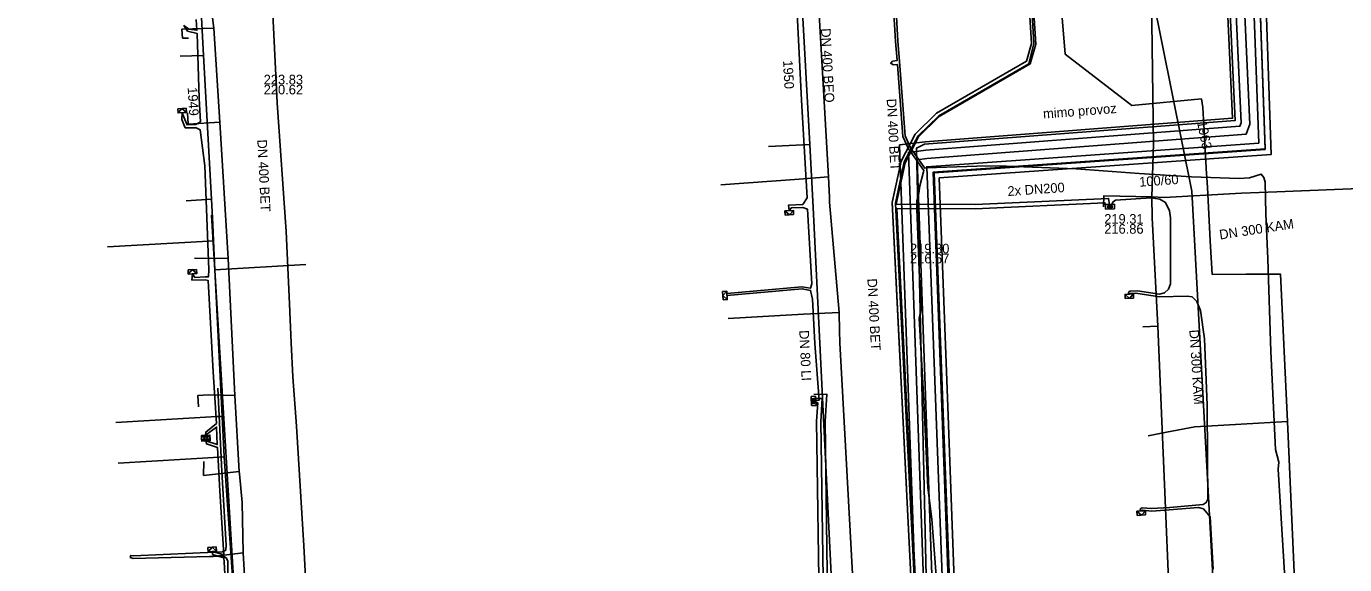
# Model space of a CAD drawing. Extents: x -599951 to -598963, y -1164095 to -1162939.
# Drawn here: x -599392 to -599282.6, y -1163043.2 to -1162998.5 of the extents above; entities that cross this region are included whole.
import ezdxf

# ---------------------------------------------------------------- set-up
doc = ezdxf.new("R2010")
doc.units = 0
for name, color, linetype in [('28', 7, 'Continuous'), ('31', 7, 'Continuous'), ('Vrstva 12', 7, 'Continuous'), ('Vrstva 13', 7, 'Continuous'), ('Vrstva 15', 7, 'Continuous'), ('Vrstva 19', 7, 'Continuous'), ('Vrstva 25', 7, 'Continuous'), ('Vrstva 26', 7, 'Continuous'), ('Vrstva 28', 7, 'Continuous'), ('Vrstva 37', 7, 'Continuous'), ('Vrstva 38', 7, 'Continuous'), ('Vrstva 41', 7, 'Continuous'), ('Vrstva 42', 7, 'Continuous'), ('Vrstva 43', 7, 'Continuous'), ('Vrstva 44', 7, 'Continuous'), ('Vrstva 55', 7, 'Continuous')]:
    doc.layers.add(name, color=color, linetype=linetype)

# ---------------------------------------------------------------- blocks, each defined once
blk = doc.blocks.new('NN630')
at = {"layer": '31'}
for points in [[(-0.003, -0.7), (-0.703, 0)], [(-0.703, -0.7), (-0.703, 0), (0.697, 0), (0.697, -0.7)], [(-0.003, -0.7), (0.697, 0)], [(-0.703, -0.7), (0.697, -0.7)]]:
    blk.add_lwpolyline(points, dxfattribs=at)
blk = doc.blocks.new('NN620')
at = {"layer": '28'}
for points in [[(0.752, 0.004), (-0.748, 0.004)], [(-0.748, 0.004), (-0.748, -0.746)], [(0.752, -0.746), (0.752, 0.004)], [(-0.748, -0.746), (0.752, -0.746)], [(0.368, -0.18), (-0.376, -0.18)], [(-0.376, -0.18), (-0.376, -0.558)], [(-0.376, -0.558), (0.368, -0.558)], [(0.321, -0.227), (-0.329, -0.227)], [(-0.329, -0.227), (-0.329, -0.51)], [(-0.329, -0.51), (0.321, -0.51)], [(0.274, -0.274), (-0.281, -0.274)], [(-0.281, -0.274), (-0.281, -0.463)], [(-0.281, -0.463), (0.274, -0.463)], [(0.227, -0.321), (-0.234, -0.321)], [(-0.234, -0.321), (-0.234, -0.416)], [(-0.234, -0.416), (0.227, -0.416)], [(-0.193, -0.369), (0.185, -0.369)], [(0.227, -0.416), (0.227, -0.321)], [(0.274, -0.463), (0.274, -0.274)], [(0.321, -0.51), (0.321, -0.227)], [(0.368, -0.558), (0.368, -0.18)]]:
    blk.add_lwpolyline(points, dxfattribs=at)

msp = doc.modelspace()

# ---------------------------------------------------------------- linework, layer by layer
at = {"layer": 'Vrstva 12'}
msp.add_lwpolyline([(-599376.65, -1163014.17), (-599374.24, -1163053.96), (-599375.34, -1163054.02), (-599372.81, -1163104.13), (-599372.73, -1163105.83), (-599379.12, -1163106.22), (-599392.02, -1163106.91), (-599391.55, -1163104.38)], dxfattribs=at)
at = {"layer": 'Vrstva 13'}
for p, q in [((-599377.319, -1163000.888), (-599379.255, -1163000.969)), ((-599326.948, -1163008.293), (-599330.381, -1163008.477)), ((-599376.655, -1163012.839), (-599378.763, -1163012.969)), ((-599376.367, -1163018.71), (-599368.809, -1163018.281))]:
    msp.add_line(p, q, dxfattribs=at)
for points in [[(-599376.539, -1163014.958), (-599376.655, -1163012.839), (-599377.319, -1163000.888), (-599378.171, -1162984.588), (-599378.45, -1162980.06), (-599378.82, -1162974.23), (-599379.15, -1162967.72), (-599379.452, -1162962.026), (-599380.077, -1162950.799), (-599380.39, -1162945.01), (-599380.421, -1162944.491), (-599380.722, -1162939.4)], [(-599326.68, -1163013.53), (-599326.948, -1163008.293), (-599327.64, -1162995.76), (-599328.043, -1162987.835), (-599328.151, -1162986.54), (-599328.478, -1162980.575), (-599328.799, -1162974.276), (-599329.08, -1162968.678), (-599329.394, -1162962.653), (-599329.655, -1162956.664), (-599329.88, -1162951.055)], [(-599287.66, -1163147.47), (-599287.596, -1163147.153), (-599291.469, -1163082.154), (-599292.48, -1163063.001), (-599295.243, -1163012.163), (-599300.148, -1162987.801), (-599300.278, -1162987.115), (-599302.071, -1162951.135)], [(-599319.824, -1163142.407), (-599319.759, -1163142.094), (-599323.979, -1163068.87), (-599326.68, -1163013.53)], [(-599370.026, -1163132.931), (-599369.957, -1163132.609), (-599371.633, -1163102.923), (-599371.78, -1163099.83), (-599374.86, -1163044.99), (-599375.586, -1163034.266), (-599375.774, -1163030.889), (-599376.367, -1163018.71), (-599376.476, -1163016.302), (-599376.539, -1163014.958)], [(-599376.476, -1163016.302), (-599376.9, -1163016.326), (-599385.282, -1163016.815)], [(-599375.774, -1163030.889), (-599376.198, -1163030.913), (-599384.58, -1163031.402)], [(-599375.586, -1163034.266), (-599376.01, -1163034.29), (-599384.392, -1163034.779)]]:
    msp.add_lwpolyline(points, dxfattribs=at)
at = {"layer": 'Vrstva 19'}
for points in [[(-599379.168, -1162939.4), (-599379.16, -1162943.1), (-599379.12, -1162943.7), (-599378.94, -1162949.75), (-599378.72, -1162955.7), (-599378.58, -1162957.14), (-599378.39, -1162963.15), (-599378, -1162969.19), (-599377.66, -1162975.24), (-599376.95, -1162984.34), (-599377.05, -1162984.82), (-599377.38, -1162991.49), (-599376.45, -1162998.64), (-599375.963, -1163006.441), (-599375.51, -1163013.7), (-599375.25, -1163017.78), (-599374.71, -1163029.16), (-599374.34, -1163035.46), (-599374.33, -1163035.67), (-599374.09, -1163038.05), (-599374.03, -1163042.23), (-599373.154, -1163056.939)], [(-599329.03, -1162941.398), (-599328.43, -1162946.79), (-599328.44, -1162948.43), (-599328.43, -1162949.96), (-599328.42, -1162952.35), (-599328.46, -1162953.86), (-599328.47, -1162954.08), (-599328.21, -1162957.68), (-599327.88, -1162963.39), (-599327.66, -1162969.43), (-599327.34, -1162975.25), (-599327.15, -1162978.91), (-599327.08, -1162980.4), (-599326.96, -1162981.47), (-599326.52, -1162989.98), (-599326.59, -1162990.17), (-599326.51, -1162991.69), (-599325.41, -1163010.98), (-599325.37, -1163011.57), (-599325.34, -1163012.71), (-599325.32, -1163013.09), (-599324.53, -1163022.27), (-599324.49, -1163023.77)], [(-599305.18, -1162946.96), (-599305.12, -1162950.24), (-599305.28, -1162950.58), (-599308.44, -1162952.65), (-599308.65, -1162953), (-599308.33, -1162968.25), (-599307.74, -1162977.05), (-599307.31, -1162982.96), (-599306.76, -1162988.68), (-599305.75, -1163000.8), (-599300.22, -1163005.05), (-599294.44, -1163004.51), (-599294.34, -1163005.23)], [(-599376.45, -1162998.64), (-599379.113, -1162998.701)], [(-599379.113, -1162998.701), (-599379.05, -1162999.45), (-599378.56, -1162999.45)], [(-599294.34, -1163005.23), (-599294.27, -1163006.21), (-599294.248, -1163006.608), (-599294.02, -1163010.75), (-599293.99, -1163010.99), (-599293.956, -1163011.482), (-599293.93, -1163011.85)], [(-599375.963, -1163006.441), (-599378.584, -1163006.603), (-599378.64, -1163005.68)], [(-599334.34, -1163011.66), (-599327.85, -1163011.19), (-599325.41, -1163010.98)], [(-599293.93, -1163011.85), (-599293.71, -1163016.31), (-599293.55, -1163019.1), (-599290.72, -1163019.08), (-599287.88, -1163019.06), (-599287.29, -1163031.32), (-599286.4, -1163051.37), (-599284.83, -1163084.5), (-599284.03, -1163097.16), (-599283.11, -1163097.11), (-599283.03, -1163098.11)], [(-599375.25, -1163017.78), (-599378.05, -1163017.74)], [(-599333.75, -1163022.75), (-599327.5, -1163022.4), (-599324.53, -1163022.27)], [(-599324.49, -1163023.77), (-599324.46, -1163024.77), (-599323.15, -1163049.03), (-599323.15, -1163049.58), (-599323.13, -1163049.8), (-599323.11, -1163050.08), (-599322.92, -1163053.42), (-599322.91, -1163053.6), (-599322.91, -1163053.64), (-599322.87, -1163053.99), (-599322.88, -1163054.21), (-599322.64, -1163058.55), (-599322.54, -1163060.9), (-599322.42, -1163062.51)], [(-599376.9, -1163029.1), (-599377.786, -1163029.161), (-599377.72, -1163030.11)], [(-599374.71, -1163029.16), (-599376.9, -1163029.1)], [(-599287.29, -1163031.32), (-599295, -1163031.77), (-599297.34, -1163032.2), (-599298.88, -1163032.512)], [(-599377.302, -1163035.804), (-599377.28, -1163034.63)], [(-599374.34, -1163035.46), (-599377.302, -1163035.804)], [(-599374.03, -1163042.23), (-599376.51, -1163042.53), (-599377.639, -1163042.573)]]:
    msp.add_lwpolyline(points, dxfattribs=at)
at = {"layer": 'Vrstva 25'}
msp.add_line((-599299.303, -1163023.441), (-599298.054, -1163023.39), dxfattribs=at)
for points in [[(-599300.733, -1162964.746), (-599300.469, -1162969.62), (-599299.949, -1162980.551), (-599299.608, -1162987.828), (-599299.004, -1162993.074), (-599298.585, -1162996.107), (-599298.467, -1163004.22), (-599298.411, -1163008.238), (-599298.555, -1163012.651)], [(-599290.017, -1162984.479), (-599289.606, -1162996.071), (-599289.16, -1163008.65), (-599316.731, -1163010.607), (-599316.004, -1163030.112), (-599315.215, -1163051.283)], [(-599298.555, -1163012.651), (-599297.531, -1163012.698), (-599291.113, -1163012.346), (-599288.176, -1163012.237), (-599277.923, -1163011.817), (-599272.947, -1163011.498), (-599270.093, -1163011.364), (-599268.714, -1163010.395), (-599267.215, -1163010.078), (-599266.581, -1163009.994), (-599263.155, -1163009.11), (-599262.534, -1163008.77), (-599262.094, -1163004.619), (-599261.61, -1163001.091), (-599260.5, -1163000.959), (-599257.859, -1163000.91), (-599227.32, -1162998.551), (-599226.298, -1162998.669), (-599225.212, -1162998.622), (-599224.037, -1162998.524)], [(-599298.555, -1163012.651), (-599302.544, -1163012.554), (-599302.586, -1163013.486)], [(-599298.555, -1163012.651), (-599298.536, -1163014.387), (-599298.054, -1163023.39)], [(-599298.054, -1163023.39), (-599296.529, -1163059.558)]]:
    msp.add_lwpolyline(points, dxfattribs=at)
at = {"layer": 'Vrstva 26'}
for points in [[(-599315.733, -1163050.809), (-599316.504, -1163030.131), (-599317.248, -1163010.143), (-599289.677, -1163008.185), (-599290.106, -1162996.089), (-599290.517, -1162984.497)], [(-599289.517, -1162984.461), (-599289.106, -1162996.054), (-599288.643, -1163009.115), (-599316.213, -1163011.072), (-599315.504, -1163030.093), (-599314.716, -1163051.265)]]:
    msp.add_lwpolyline(points, dxfattribs=at)
at = {"layer": 'Vrstva 37'}
for points in [[(-599290.485, -1162978.048), (-599290.017, -1162984.479), (-599289.156, -1163008.706), (-599316.634, -1163010.66), (-599315.123, -1163051.266), (-599334.6, -1163052.28), (-599334.32, -1163059.62), (-599376.96, -1163062.17), (-599376.46, -1163077.4), (-599383.092, -1163077.483)], [(-599292.436, -1162978.249), (-599291.143, -1163006.497), (-599291.245, -1163006.778), (-599317.317, -1163008.775), (-599318.78, -1163008.949), (-599316.627, -1163069.826), (-599308.259, -1163069.607)], [(-599292.935, -1162978.272), (-599291.652, -1163006.308), (-599317.451, -1163008.283), (-599318.097, -1163008.6), (-599316.707, -1163069.9), (-599308.159, -1163069.65)]]:
    msp.add_lwpolyline(points, dxfattribs=at)
at = {"layer": 'Vrstva 38'}
for points in [[(-599308.24, -1163070.306), (-599317.302, -1163070.544), (-599319.502, -1163008.33), (-599317.385, -1163008.078), (-599291.861, -1163006.123), (-599293.135, -1162978.281)], [(-599291.737, -1162978.217), (-599290.437, -1163006.604), (-599290.741, -1163007.442), (-599317.249, -1163009.471), (-599318.058, -1163009.568), (-599315.952, -1163069.108), (-599308.277, -1163068.907)]]:
    msp.add_lwpolyline(points, dxfattribs=at)
at = {"layer": 'Vrstva 42'}
for points in [[(-599326.633, -1163029.066), (-599325.551, -1163029.042), (-599325.699, -1163031.314), (-599325.457, -1163048.064), (-599325.288, -1163054.96), (-599318.265, -1163054.466), (-599318.078, -1163053.65), (-599318.348, -1163048.216), (-599318.451, -1163046.377), (-599320.112, -1163013.118), (-599319.388, -1163009.694), (-599318.216, -1163007.447), (-599316.433, -1163005.686), (-599308.957, -1163001.374), (-599308.544, -1162999.916), (-599309.499, -1162984.786), (-599310.569, -1162962.287)], [(-599290.485, -1162978.048), (-599290.017, -1162984.479), (-599289.156, -1163008.706), (-599316.634, -1163010.66), (-599315.123, -1163051.266), (-599334.6, -1163052.28), (-599334.32, -1163059.62), (-599376.96, -1163062.17), (-599376.46, -1163077.4), (-599383.092, -1163077.483)], [(-599302.078, -1163013.294), (-599302.148, -1163012.777), (-599313.241, -1163013.297), (-599319.783, -1163013.256), (-599319.055, -1163009.813), (-599317.931, -1163007.657), (-599316.219, -1163005.967), (-599308.659, -1163001.606), (-599308.191, -1162999.954), (-599309.15, -1162984.766), (-599309.291, -1162981.878), (-599301.679, -1162981.183), (-599285.76, -1162980.219), (-599285.692, -1162978.677)], [(-599292.935, -1162978.272), (-599291.652, -1163006.308), (-599317.451, -1163008.283), (-599318.097, -1163008.6), (-599316.707, -1163069.9), (-599308.159, -1163069.65)], [(-599328.207, -1162993.479), (-599327.641, -1163004.615), (-599327.196, -1163012.72), (-599327.555, -1163013.272), (-599328.739, -1163013.347), (-599328.676, -1163013.796), (-599328.492, -1163013.555), (-599327.546, -1163013.523), (-599327.167, -1163013.667), (-599326.782, -1163019.864), (-599326.91, -1163020.241), (-599327.613, -1163020.122), (-599333.851, -1163020.684), (-599333.843, -1163020.836), (-599327.592, -1163020.282), (-599326.895, -1163020.424), (-599326.733, -1163021.153), (-599326.545, -1163024.846), (-599326.193, -1163029.554), (-599326.471, -1163029.598)], [(-599377.924, -1162997.902), (-599377.856, -1162998.804), (-599378.533, -1162998.701), (-599378.935, -1162998.416), (-599378.628, -1162998.877), (-599377.848, -1162999.069), (-599377.658, -1163004.469), (-599377.564, -1163006.408), (-599377.94, -1163006.645), (-599378.671, -1163006.664), (-599378.853, -1163006.215), (-599379.08, -1163005.653), (-599379.105, -1163006.21), (-599378.83, -1163006.901), (-599377.917, -1163006.9), (-599377.589, -1163007.077), (-599377.201, -1163010.064), (-599376.863, -1163018.698), (-599376.9, -1163019.306), (-599377.171, -1163019.287), (-599378.028, -1163019.343), (-599378.226, -1163019.042), (-599378.278, -1163019.562), (-599377.177, -1163019.556), (-599376.935, -1163019.587), (-599376.51, -1163027.178), (-599376.239, -1163031.481), (-599377.122, -1163032.2), (-599377.131, -1163032.463), (-599376.222, -1163031.786), (-599376.172, -1163033.233), (-599377.105, -1163032.923), (-599377.071, -1163033.184), (-599376.158, -1163033.474), (-599375.961, -1163037.107), (-599375.627, -1163042.385), (-599376.573, -1163042.115), (-599376.559, -1163042.362), (-599375.619, -1163042.633), (-599375.606, -1163042.967), (-599375.312, -1163048.07)], [(-599383.651, -1163066.976), (-599383.04, -1163066.909), (-599382.022, -1163066.204), (-599382.174, -1163059.783), (-599381.318, -1163059.25), (-599375.097, -1163058.41), (-599367.103, -1163057.865), (-599361.976, -1163057.256), (-599337.823, -1163055.997), (-599331.491, -1163055.747), (-599327.851, -1163055.894), (-599326.518, -1163055.909), (-599325.108, -1163055.298), (-599317.982, -1163054.797), (-599317.726, -1163053.681), (-599317.998, -1163048.198), (-599318.101, -1163046.358), (-599319.737, -1163013.607), (-599313.234, -1163013.647), (-599302.452, -1163013.142), (-599302.43, -1163013.302)], [(-599293.47, -1163043.58), (-599293.73, -1163039.24), (-599294.28, -1163038.56), (-599294.68, -1163038.46), (-599297.13, -1163038.66), (-599298.563, -1163038.756), (-599299.329, -1163038.698), (-599299.448, -1163038.752), (-599299.519, -1163038.667), (-599299.491, -1163038.578), (-599299.447, -1163038.519), (-599299.361, -1163038.499), (-599298.583, -1163038.557), (-599297.06, -1163038.47), (-599294.29, -1163038.22), (-599294.05, -1163038.06), (-599293.91, -1163037.77), (-599293.94, -1163034.37), (-599293.98, -1163029.96), (-599294.2, -1163024.44), (-599294.53, -1163022.1), (-599294.82, -1163021.35), (-599295.22, -1163020.97), (-599295.64, -1163020.89), (-599297.93, -1163020.96), (-599299.9, -1163020.664), (-599300.32, -1163020.681), (-599300.439, -1163020.735), (-599300.51, -1163020.65), (-599300.482, -1163020.561), (-599300.438, -1163020.502), (-599300.352, -1163020.482), (-599299.75, -1163020.457), (-599297.92, -1163020.73), (-599297.5, -1163020.63), (-599297.18, -1163020.33), (-599297.01, -1163019.88), (-599297.01, -1163014.38), (-599297.1, -1163013.8), (-599297.43, -1163013.13), (-599297.89, -1163012.83), (-599298.62, -1163012.73), (-599301.592, -1163012.936), (-599301.785, -1163013.05), (-599301.865, -1163013.2), (-599301.865, -1163013.275)], [(-599383.689, -1163066.628), (-599383.231, -1163066.578), (-599382.434, -1163066.081), (-599382.551, -1163059.616), (-599381.439, -1163058.913), (-599375.132, -1163058.062), (-599367.136, -1163057.516), (-599362.006, -1163056.907), (-599337.839, -1163055.647), (-599331.491, -1163055.397), (-599327.842, -1163055.544), (-599326.589, -1163055.558), (-599325.634, -1163055.144), (-599325.807, -1163048.071), (-599326.049, -1163031.305), (-599325.925, -1163029.401), (-599326.626, -1163029.416)], [(-599376.11, -1163028.54), (-599375.78, -1163035.47), (-599375.44, -1163041.6), (-599375.46, -1163042), (-599375.74, -1163042.16), (-599383.11, -1163042.491), (-599383.355, -1163042.445), (-599383.39, -1163042.608), (-599383.14, -1163042.693), (-599375.76, -1163042.51), (-599375.58, -1163042.56), (-599375.43, -1163042.65), (-599375.3, -1163042.9), (-599375.25, -1163048.03)], [(-599326.618, -1163029.766), (-599326.299, -1163029.759), (-599326.399, -1163031.296), (-599326.157, -1163048.078), (-599325.996, -1163054.643)]]:
    msp.add_lwpolyline(points, dxfattribs=at)
at = {"layer": 'Vrstva 44'}
for points in [[(-599318.451, -1163046.377), (-599319.866, -1163018.049), (-599320.112, -1163013.118), (-599319.388, -1163009.694), (-599318.216, -1163007.447), (-599316.433, -1163005.686), (-599308.957, -1163001.374), (-599308.544, -1162999.916), (-599309.499, -1162984.786)], [(-599309.232, -1162984.758), (-599308.369, -1162999.891), (-599308.787, -1163001.599), (-599316.247, -1163005.902), (-599317.975, -1163007.579), (-599319.141, -1163009.74), (-599319.852, -1163013.162), (-599318.18, -1163046.456)]]:
    msp.add_lwpolyline(points, dxfattribs=at)
at = {"layer": 'Vrstva 55'}
for points in [[(-599368.26, -1163055.24), (-599368.99, -1163041.65), (-599369.59, -1163031.7), (-599369.88, -1163027.6), (-599370.04, -1163024.77), (-599370.18, -1163021.55), (-599370.44, -1163015.52), (-599371.19, -1163004.83), (-599371.877, -1162990.601)], [(-599316.28, -1163046.67), (-599316.83, -1163039.44), (-599317.15, -1163036.79), (-599317.49, -1163029.57), (-599317.89, -1163022.77), (-599317.73, -1163021.94), (-599317.89, -1163018.75), (-599318.07, -1163013.64), (-599318.09, -1163012.99), (-599317.9, -1163012.35), (-599317.84, -1163011.74), (-599317.51, -1163010.56), (-599317.506, -1163010.45), (-599318.771, -1163008.651), (-599319.228, -1163007.635), (-599319.692, -1163001.636), (-599320.055, -1163001.683), (-599320.24, -1163001.54), (-599320.089, -1163001.381), (-599319.717, -1163001.33), (-599319.86, -1162999.737), (-599320.17, -1162994.104)], [(-599287.53, -1163044.33), (-599288.07, -1163035.27), (-599288.02, -1163034.69), (-599288.3, -1163033.63), (-599288.67, -1163025.5), (-599288.92, -1163017.79), (-599289.09, -1163014.06), (-599289.15, -1163011.42), (-599289.27, -1163011.04), (-599289.48, -1163010.75), (-599290.46, -1163011.08), (-599291.32, -1163011.11), (-599295.27, -1163010.98), (-599299.62, -1163010.71), (-599304.84, -1163010.33), (-599311.34, -1163010.06), (-599313.09, -1163010.1), (-599317.27, -1163010.24), (-599317.412, -1163010.261), (-599318.589, -1163008.569), (-599319.032, -1163007.585), (-599319.51, -1163001.392), (-599319.66, -1162999.723), (-599319.97, -1162994.096)]]:
    msp.add_lwpolyline(points, dxfattribs=at)

# ---------------------------------------------------------------- block references
at = {"layer": 'Vrstva 43'}
for name, p, xscale, yscale, rotation in [('NN630', (-599379.08, -1163005.653), 0.5000000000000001, 0.5, -177.00000000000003), ('NN630', (-599328.676, -1163013.796), 0.5, 0.5000000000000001, 4.000000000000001), ('NN620', (-599302.043, -1163013.282), 0.5000000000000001, 0.4999999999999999, 2), ('NN630', (-599378.226, -1163019.042), 0.5000000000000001, 0.5, -177.00000000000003), ('NN630', (-599333.843, -1163020.836), 0.5, 0.5000000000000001, -86), ('NN630', (-599300.439, -1163020.735), 0.5000000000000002, 0.4999999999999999, 3.0000000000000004), ('NN620', (-599326.471, -1163029.598), 0.5000000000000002, 0.4999999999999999, -87), ('NN630', (-599377.131, -1163032.463), 0.5000000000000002, 0.4999999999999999, 3.0000000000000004), ('NN630', (-599377.105, -1163032.923), 0.5000000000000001, 0.5, -177.00000000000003), ('NN630', (-599299.448, -1163038.752), 0.5000000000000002, 0.4999999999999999, 3.0000000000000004), ('NN630', (-599376.573, -1163042.115), 0.5, 0.5000000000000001, -176.00000000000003)]:
    msp.add_blockref(name, p, dxfattribs=dict(at, xscale=xscale, yscale=yscale, rotation=rotation))

# ---------------------------------------------------------------- texts
at = {"layer": 'Vrstva 12'}
for s, rotation, p in [('DN 400 BEO', 273.04371, (-599326.044, -1162998.66)), ('DN 400 BET', 273.04371, (-599320.581, -1163004.507)), ('DN 400 BET', 272.8998, (-599372.844, -1163007.903)), ('DN 300 KAM', 8.65166, (-599292.895, -1163016.2)), ('DN 400 BET', 272.95709, (-599322.185, -1163019.449)), ('DN 300 KAM', 273.70194, (-599295.452, -1163023.706))]:
    msp.add_text(s, height=0.8, rotation=rotation, dxfattribs=at).set_placement(p)
for s, p in [('223.83', (-599372.314, -1163003.301)), ('220.62', (-599372.314, -1163004.133)), ('219.31', (-599302.517, -1163014.881)), ('216.86', (-599302.517, -1163015.713)), ('219.80', (-599318.646, -1163017.347)), ('216.67', (-599318.646, -1163018.179))]:
    msp.add_text(s, height=0.8, dxfattribs=at).set_placement(p)
at = {"layer": 'Vrstva 15'}
for s, rotation, p in [('1950', 272.95709, (-599329.188, -1163001.323)), ('1949', 273.18628, (-599378.626, -1163003.559)), ('1963', 281.37957, (-599294.816, -1163006.422)), ('DN 80 LI', 272.79424, (-599327.84, -1163023.746))]:
    msp.add_text(s, height=0.8, rotation=rotation, dxfattribs=at).set_placement(p)
at = {"layer": 'Vrstva 28'}
for s, p in [('100/60', (-599299.583, -1163011.808)), ('2x DN200', (-599310.519, -1163012.583))]:
    msp.add_text(s, height=0.8, rotation=4.06069, dxfattribs=at).set_placement(p)
at = {"layer": 'Vrstva 41'}
msp.add_text('mimo provoz', height=0.8, rotation=4.37841, dxfattribs=at).set_placement((-599307.566, -1163006.146))

doc.saveas('drawing.dxf')
